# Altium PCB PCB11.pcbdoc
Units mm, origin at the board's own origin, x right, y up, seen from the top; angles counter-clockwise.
Board outline 72.14 x 44.96 mm, 2 copper layers (Top Layer, Bottom Layer); 25 components, 15 nets, 61 pads, 84 vias.
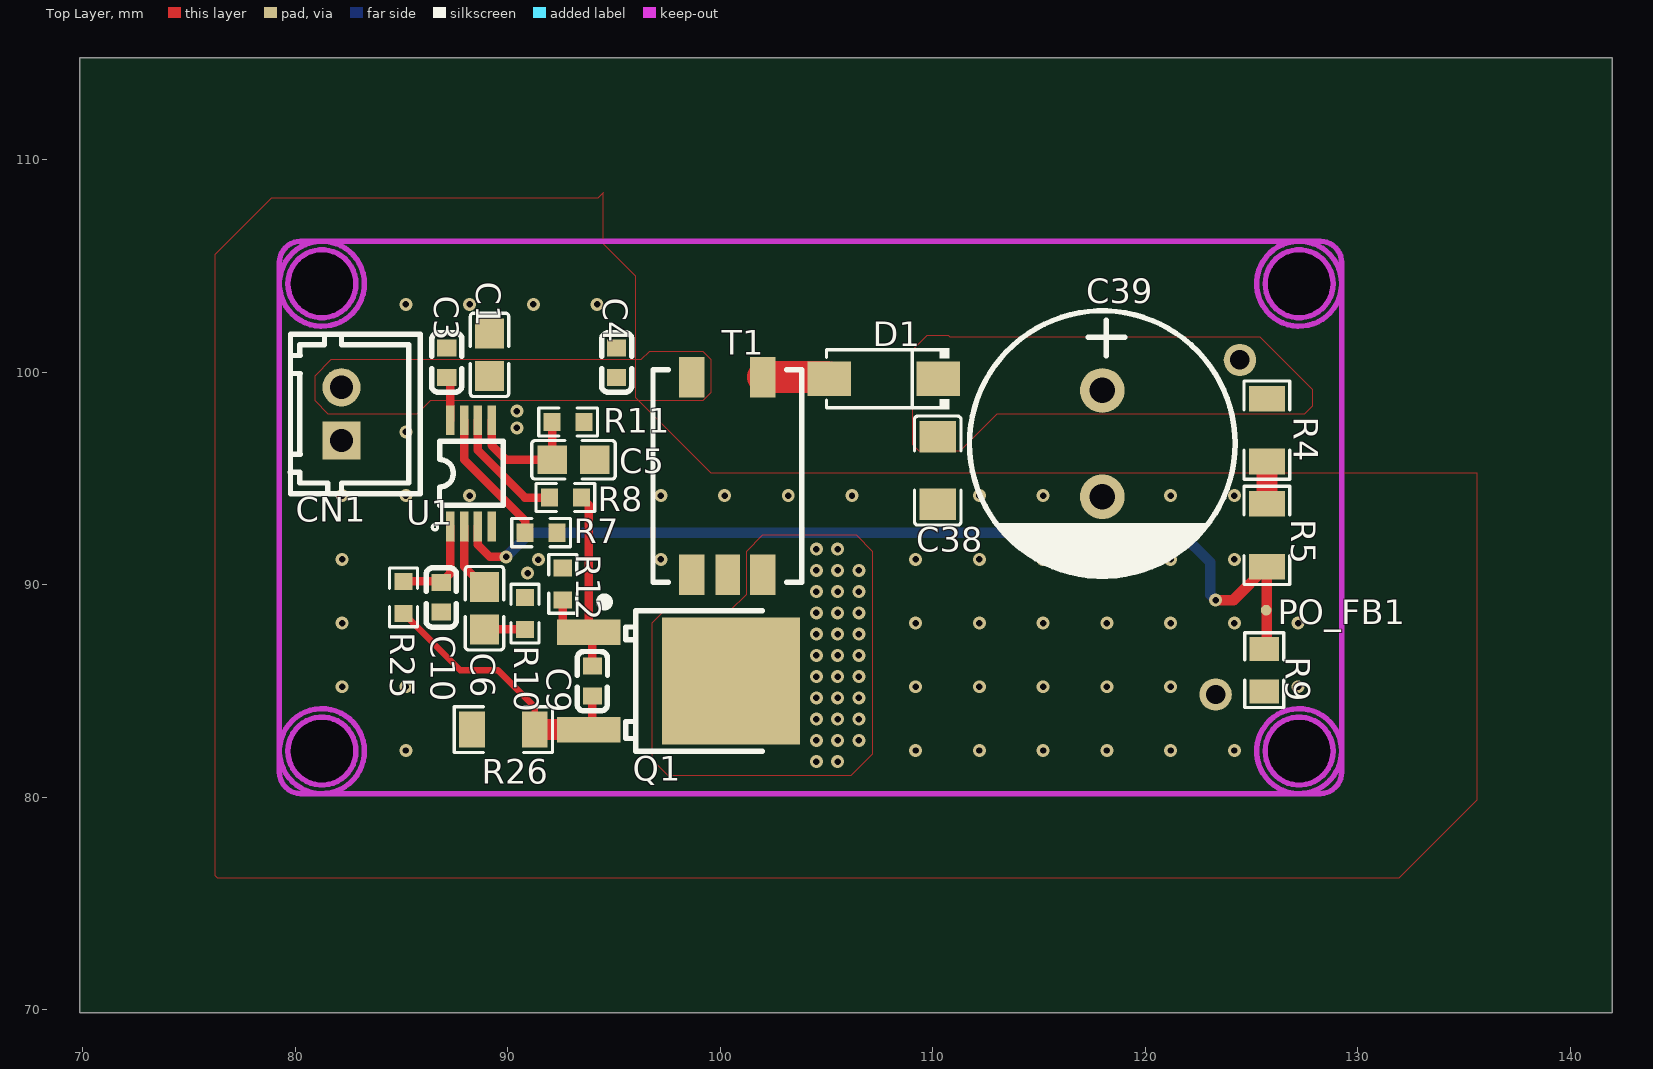
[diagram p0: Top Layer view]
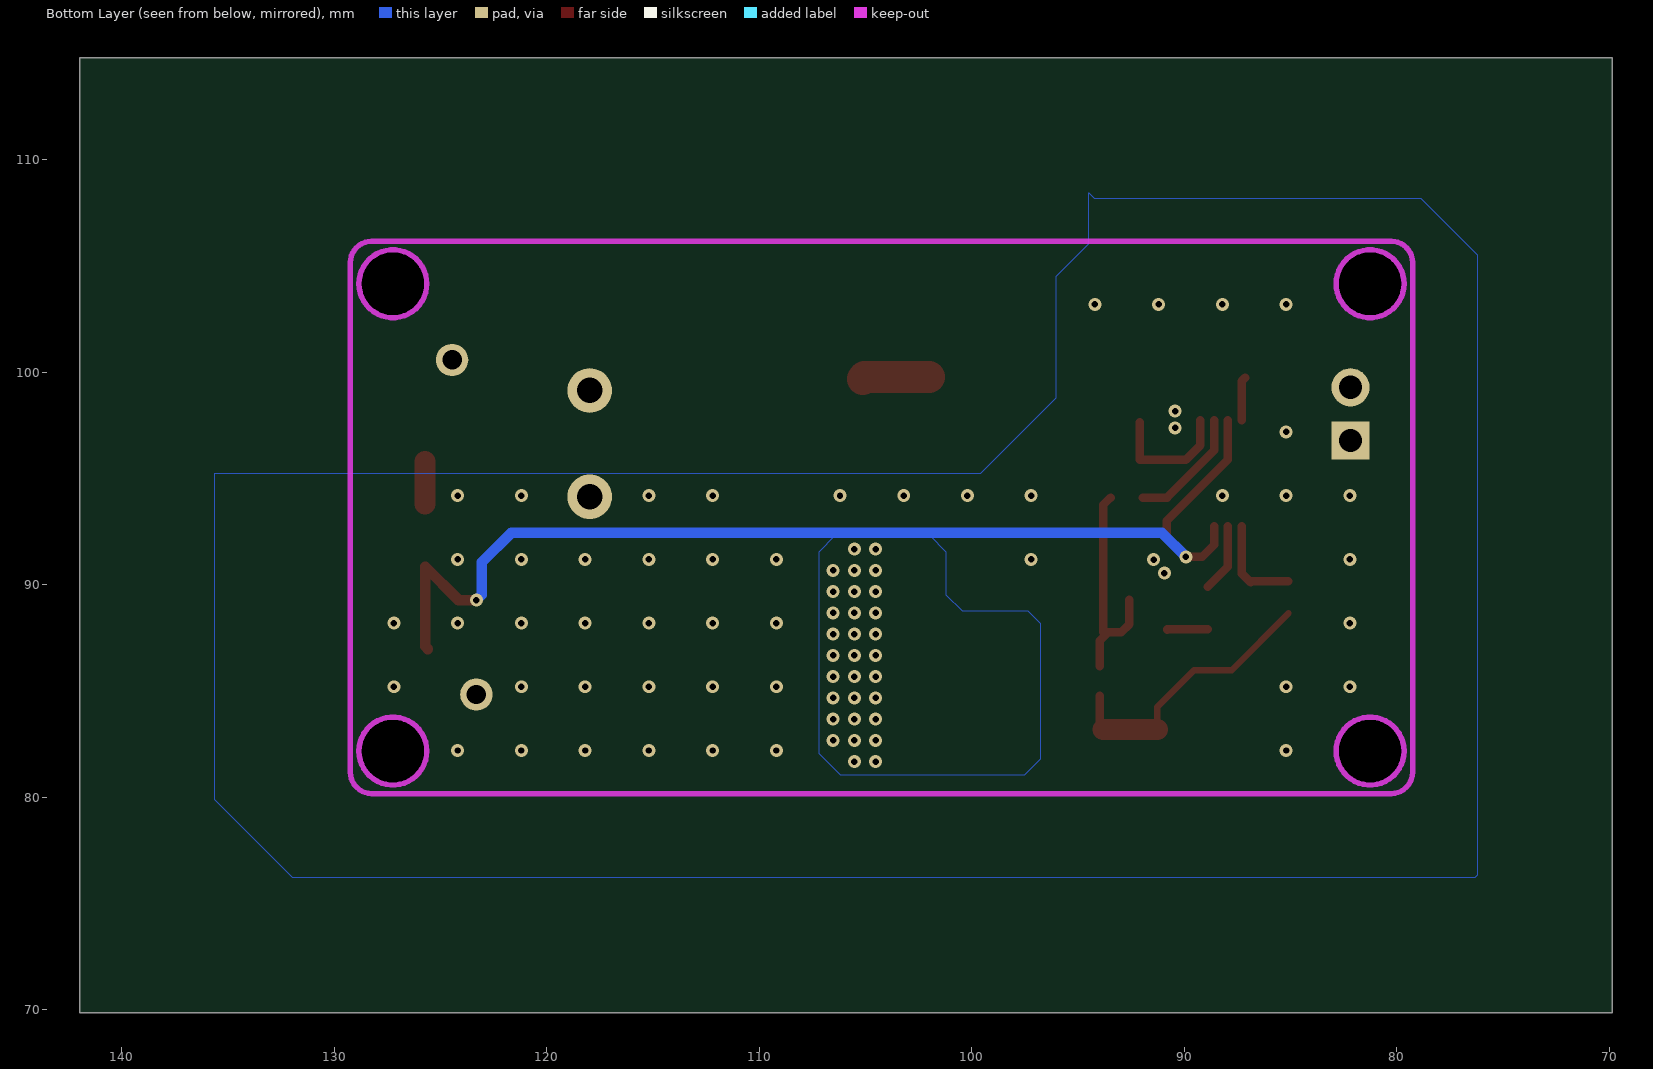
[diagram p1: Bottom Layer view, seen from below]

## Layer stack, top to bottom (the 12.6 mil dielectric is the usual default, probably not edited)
Top Layer: signal copper (thickness not stored)
Dielectric: dielectric 0.32, FR-4, Dk 4.8
Bottom Layer: signal copper (thickness not stored)

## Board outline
141.986,69.85 69.85,69.85 69.85,114.808 141.986,114.808
cut-out: 82.848,104.172 ccw(c81.248,104.163) 79.648,104.172 ccw(c81.248,104.181)
cut-out: 82.848,82.172 ccw(c81.248,82.163) 79.648,82.172 ccw(c81.248,82.181)
cut-out: 128.848,104.172 ccw(c127.248,104.172) 125.648,104.172 ccw(c127.248,104.172)
cut-out: 128.848,82.172 ccw(c127.248,82.172) 125.648,82.172 ccw(c127.248,82.172)

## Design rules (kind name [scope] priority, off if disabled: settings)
Clearance copperThickness1oz [All] p1: gap=0.178 ignorepadtopadclearanceinfootprint=FALSE except(0.102: Track-Track; 0.152: Track-SMDPad SMDPad-SMDPad Track-THPad SMDPad-THPad THPad-THPad Track-Via SMDPad-Via THPad-Via Via-Via Track-Fill SMDPad-Fill THPad-Fill Via-Fill Fill-Fill SMDPad-Region THPad-Region Via-Region Fill-Region Region-Region Track-Poly SMDPad-Poly THPad-Poly Via-Poly Fill-Poly Poly-Poly Track-Text SMDPad-Text THPad-Text Via-Text Fill-Text Region-Text Poly-Text Text-Text Track-Hole SMDPad-Hole THPad-Hole Via-Hole Fill-Hole Region-Hole Poly-Hole Text-Hole; 0.3: Track-Region Region-Poly Track-Sheet SMDPad-Sheet THPad-Sheet Via-Sheet Fill-Sheet Region-Sheet Poly-Sheet Text-Sheet Sheet-Hole)
Clearance copperThickness2oz [All] p1: gap=0.178 ignorepadtopadclearanceinfootprint=FALSE except(0.152: Track-SMDPad SMDPad-SMDPad Track-THPad SMDPad-THPad THPad-THPad Track-Via SMDPad-Via THPad-Via Via-Via Track-Fill SMDPad-Fill THPad-Fill Via-Fill Fill-Fill SMDPad-Region THPad-Region Via-Region Fill-Region Region-Region Track-Poly SMDPad-Poly THPad-Poly Via-Poly Fill-Poly Poly-Poly Track-Text SMDPad-Text THPad-Text Via-Text Fill-Text Region-Text Poly-Text Text-Text Track-Hole SMDPad-Hole THPad-Hole Via-Hole Fill-Hole Region-Hole Poly-Hole Text-Hole; 0.203: Track-Track; 0.3: Track-Region Region-Poly Track-Sheet SMDPad-Sheet THPad-Sheet Via-Sheet Fill-Sheet Region-Sheet Poly-Sheet Text-Sheet Sheet-Hole)
DiffPairsRouting differentialPair [All] p1: maxuncoupledlength=10 maxlimit=5.9843 mostfreqgap=5.9843 toplayer_minwidth=5 toplayer_prefwidth=10 toplayer_maxwidth=100 bottomlayer_minwidth=5 bottomlayer_prefwidth=10 bottomlayer_maxwidth=100
PasteMaskExpansion pasteMaskExpansion [All] p1:
PlaneConnect innerPlane [All] p1: planeconnectstyle=Relief reliefexpansion=0.508 reliefentries=4 reliefconductorwidth=0.254 reliefairgap=0.254
PolygonConnect copperRegion [All] p1: connectstyle=Direct reliefentries=4 reliefconductorwidth=10 polygonreliefangle="90 Angle" airgapwidth=10
RoutingVias viaSize [All] p1: viastyle="Through Hole" holewidth=12.0078 minholewidth=11.811 maxholewidth=248.0314 width=24.0158 minwidth=19.685 maxwidth=393.7008
SolderMaskExpansion solderMaskExpansion [All] p1: useseparateexpansions=TRUE expansion=2.0079 expansionbottom=2.0079
Width copperThickness1oz [All] p1: maxlimit=100 minlimit=5 preferedwidth=10
Width copperThickness2oz [All] p1: maxlimit=100 minlimit=8 preferedwidth=10

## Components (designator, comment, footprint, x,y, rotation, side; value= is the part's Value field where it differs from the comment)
C1 "0805X106K250NT" C0805 89.138,100.822 r270 top
C3 "0603B104K500NT" C0603 87.122,100.457 r270 top
C4 "0603B104K500NT" C0603 95.123,100.457 r270 top
C5 "0805X106K250NT" C0805 93.091,95.885 r180 top
C6 "0805X106K250NT" C0805 88.9,88.9 r90 top
C9 "CC0603KRX7R9BB102" C0603 93.98,85.471 r90 top
C10 "0603B104K500NT" C0603 86.868,89.408 r90 top
C38 "1206B104K251NT_C2909525" C1206 110.236,95.377 r90 top
C39 "EGS2EM470W16OT" CAP-TH_BD12.5-P5.00-D0.6-FD 117.983,96.647 r270 top
CN1 "ZX-XH2.54-2PZZ" CONN-TH_2P-P2.50_HX25003-2A 82.169,98.044 r90 top
D1 "ES1J_C412438" SMA_L4.4-W2.8-LS5.4-RD 107.696,99.695 r180 top
PO_FB1 "Test-Point" Test-Point-0.5mm 125.694,88.807 r0 top
Q1 "NCEP02515K" TO-252-3_L6.6-W6.1-P4.58-LS10.1-BR-2 97.155,85.471 r180 top
R4 "1206W4F1003T5E" R1206 125.73,97.282 r270 top
R5 "1206W4F1003T5E" R1206 125.73,92.329 r270 top
R7 "0603WAF1003T5E" R0603 91.567,92.456 r180 top
R8 "0603WAF100JT5E" R0603 92.71,94.107 r0 top
R9 "0805W8F1501T5E" R0805 125.603,85.979 r90 top
R10 "0603WAF1002T5E" R0603 90.805,88.646 r270 top
R11 "0603WAF200JT5E" R0603 92.837,97.663 r180 top
R12 "0603WAF1002T5E" R0603 92.583,90.043 r270 top
R25 "0603WAF200JT5E" R0603 85.09,89.408 r270 top
R26 "1206W4F100LT5E" R1206 89.789,83.185 r0 top
T1 "TTRN-060S-013-T" TTRN-060S-013 100.33,95.123 r0 top
U1 "SiLM6478-AQ/Boost升压芯片" MSOP-8_L3.0-W3.0-P0.65-LS4.9-TL 88.265,95.25 r90 top

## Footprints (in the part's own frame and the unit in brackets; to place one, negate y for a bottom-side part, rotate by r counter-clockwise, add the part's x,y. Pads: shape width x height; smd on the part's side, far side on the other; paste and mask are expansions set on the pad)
C0603 [mm]
  rect 0.8x0.9 smd: 1(-0.7,0) 2(0.7,0)
  silkscreen extent -1.41,-0.71 1.39,0.72
C0805 [mm]
  rect 1.41x1.35 smd: 1(-1,0) 2(1,0)
  silkscreen extent -1.96,-0.9 1.96,0.9
C1206 [mm]
  rect 1.485x1.728 smd: 1(-1.593,0) 2(1.593,0)
  silkscreen extent -2.56,-1.09 2.56,1.09
CAP-TH_BD12.5-P5.00-D0.6-FD [mm]
  round 2.1 hole 1.2: 1(-2.5,0) 2(2.5,0)
  silkscreen extent -6.25,-6.25 6.25,6.25
CONN-TH_2P-P2.50_HX25003-2A [mm]
  rect 1.8x1.8 hole 1.1: 1(-1.25,0)
  round 1.8 hole 1.1: 2(1.25,0)
  silkscreen extent -3.75,-3.7 3.75,2.41
MSOP-8_L3.0-W3.0-P0.65-LS4.9-TL [mil]
  rect 55x16 smd: 1(-98.5,38.39) 2(-98.5,12.8) 3(-98.5,-12.8) 4(-98.5,-38.39) 5(98.5,-38.39) 6(98.5,-12.8) 7(98.5,12.8) 8(98.5,38.39)
  silkscreen extent -105,-60 60,72
R0603 [mm]
  rect 0.806x0.864 smd: 1(-0.753,0) 2(0.753,0)
  silkscreen extent -1.39,-0.66 1.39,0.66
R0805 [mm]
  rect 1.133x1.377 smd: 1(-1,0) 2(1,0)
  silkscreen extent -1.76,-0.92 1.76,0.92
R1206 [mm]
  rect 1.208x1.701 smd: 1(-1.479,0) 2(1.479,0)
  silkscreen extent -2.31,-1.08 2.31,1.08
SMA_L4.4-W2.8-LS5.4-RD [mm]
  rect 2.046x1.62 smd: 1(-2.565,0) 2(2.565,0)
  silkscreen extent -3.08,-1.44 2.7,1.44
Test-Point-0.5mm [mm]
  round 0.5 smd: 1(0,0)
TO-252-3_L6.6-W6.1-P4.58-LS10.1-BR-2 [mm]
  rect 3x1.2 smd: 1(3.342,-2.285) 3(3.342,2.285)
  rect 6.5x6 smd: 2(-3.343,0)
  silkscreen extent -4.83,-3.92 2.81,3.3
TTRN-060S-013 [mm]
  rect 1.2x1.9 smd: 1(-1.675,4.65) 2(1.675,4.651) 3(-1.675,-4.65) 5(1.675,-4.651)
  rect 1.15x1.9 smd: EMPTY(0.025,-4.65)
  silkscreen extent -3.5,-5 3.5,5

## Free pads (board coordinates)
  round 1.524 hole 0.914: 9(124.46,100.584) 10(123.317,84.836)

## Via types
v1: diameter 0.61, hole 0.304, Top Layer to Bottom Layer, 47 vias
v2: diameter 0.61, hole 0.305, Top Layer to Bottom Layer, 37 vias

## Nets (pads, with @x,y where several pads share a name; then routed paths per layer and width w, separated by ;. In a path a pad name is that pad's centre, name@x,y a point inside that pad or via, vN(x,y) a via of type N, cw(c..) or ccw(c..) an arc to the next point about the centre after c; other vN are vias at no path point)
$1N991: R7.2 U1.7 | length 6.5
  Top Layer w0.4: U1.7 87.94,95.895 90.814,93.022 R7.2
$1N997: C5.2 R11.2 U1.5 | length 6.1
  Top Layer w0.4: U1.5 89.24,96.561 89.916,95.885 C5.2 92.084,95.892 R11.2
$1N1005: C6.1 R10.2 | length 1.9
  Top Layer w0.4: C6.1 90.798,87.9 R10.2
$1N1007: C6.2 U1.2 | length 3.2
  Top Layer w0.4: U1.2 87.94,90.86 C6.2
$1N1020: C9.2 Q1.1 R8.2 R12.2 | length 10.8
  Top Layer w0.4: R12.2 92.583,88.138 92.965,87.756 Q1.1@93.579,87.756 ; R8.2 93.813,93.758 Q1.1 Q1.1@93.579,87.756 ; C9.2 93.98,87.355 Q1.1@93.579,87.756
$1N1033: C9.1 Q1.3 R25.2 R26.2 | length 13.3
  Top Layer w0.3: R25.2 87.766,85.979 89.535,85.979 91.268,84.246 R26.2
  Top Layer w0.4: Q1.3 93.98,83.354 C9.1
  Top Layer w1: R26.2 Q1.3
$1N1040: D1.2 T1.2 | length 3.2
  Top Layer w1.5: T1.2 105.052,99.774 D1.2
$1N1047: R4.2 R5.1 | length 2
  Top Layer w1: R5.1 R4.2
$1N1060: Q1.2 T1.5
  other v2: 104.521,81.678 105.521,81.678 104.521,82.678 105.521,82.678 106.521,82.678 104.521,83.678 105.521,83.678 106.521,83.678 104.521,84.678 105.521,84.678 106.521,84.678 104.521,85.678 105.521,85.678 106.521,85.678 104.521,86.678 105.521,86.678 106.521,86.678 104.521,87.678 105.521,87.678 106.521,87.678 104.521,88.678 105.521,88.678 106.521,88.678 104.521,89.678 105.521,89.678 106.521,89.678 104.521,90.678 105.521,90.678 106.521,90.678 104.521,91.678 105.521,91.678
DR: R8.1 U1.6 | length 5.7
  Top Layer w0.4: U1.6 88.59,96.322 90.805,94.107 R8.1
FB: 
GND: C1.1 C3.1 C4.1 C5.1 C10.1 C38.1 C39.2 CN1.1 pad.10 R7.1 R9.1 R10.1 R11.1 R12.1 R26.1 T1.3 U1.4
  other v1: 85.2,82.2 109.2,82.2 112.2,82.2 115.2,82.2 118.2,82.2 121.2,82.2 124.2,82.2 82.2,85.2 85.2,85.2 109.2,85.2 112.2,85.2 115.2,85.2 118.2,85.2 121.2,85.2 127.2,85.2 82.2,88.2 109.2,88.2 112.2,88.2 115.2,88.2 118.2,88.2 121.2,88.2 124.2,88.2 127.2,88.2 82.2,91.2 97.2,91.2 109.2,91.2 112.2,91.2 115.2,91.2 118.2,91.2 121.2,91.2 124.2,91.2 82.2,94.2 85.2,94.2 88.2,94.2 97.2,94.2 100.2,94.2 103.2,94.2 106.2,94.2 112.2,94.2 115.2,94.2 121.2,94.2 124.2,94.2 85.2,97.2 85.2,103.2 88.2,103.2 91.2,103.2 94.2,103.2
  other v2: 90.932,90.551 91.44,91.186 90.424,97.385 90.424,98.171
HV: C38.2 C39.1 D1.1 pad.9 R4.1
ISEN: C10.2 R25.1 U1.1 | length 4.6
  Top Layer w0.4: R25.1 86.815,90.161 C10.2 87.29,90.53 U1.1
VIN: C1.2 C3.2 C4.2 CN1.2 T1.1 U1.8 | length 2.1
  Top Layer w0.4: C3.2 87.29,99.589 U1.8
pads on no net: PO_FB1.1 R5.2 R9.2 T1.EMPTY U1.3
copper on no net: | length 45.5
  Top Layer w0.4: 88.59,92.748 88.59,91.877 89.154,91.313 v2(89.916,91.313)
  Top Layer w0.5: v2(123.317,89.281) 124.161,89.281 125.73,90.85 125.73,87.106 125.603,86.979
  Bottom Layer w0.5: v2(89.916,91.313) 91.059,92.456 121.666,92.456 123.063,91.059 123.063,89.535 v2(123.317,89.281)

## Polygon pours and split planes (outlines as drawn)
VIN on Top Layer (solid, remove dead copper): 81.661,100.584 80.899,99.822 80.899,98.679 81.534,98.044 85.725,98.044 86.36,98.679 99.187,98.679 99.568,99.06 99.568,100.584 99.187,100.965 96.647,100.965 96.266,100.584
$1N1060 on Bottom Layer (solid, remove dead copper, pour order 10): 101.981,92.329 101.219,91.567 101.219,89.535 100.457,88.773 97.361,88.773 96.774,88.186 96.774,81.788 97.536,81.026 106.172,81.026 107.188,82.042 107.188,91.567 106.426,92.329
$1N1060 on Top Layer (solid, remove dead copper, pour order 4): 101.981,92.329 101.219,91.567 101.219,89.535 100.457,88.773 97.361,88.773 96.774,88.186 96.774,81.788 97.536,81.026 106.172,81.026 107.188,82.042 107.188,91.567 106.426,92.329
GND on Top Layer (solid, remove dead copper, pour order 6): 78.867,108.204 76.2,105.537 76.2,76.327 76.327,76.2 131.953,76.2 135.636,79.883 135.636,95.25 99.568,95.25 96.012,98.806 96.012,104.521 94.488,106.045 94.488,108.458 94.234,108.204
HV on Top Layer (solid, remove dead copper, pour order 8): 109.728,101.727 109.035,101.034 109.035,96.619 109.35,96.303 111.289,96.303 113.03,98.044 127.508,98.044 127.889,98.425 127.889,99.187 125.425,101.651 110.82,101.651 110.744,101.727
GND on Bottom Layer (solid, remove dead copper, pour order 18): 78.867,108.204 76.2,105.537 76.2,76.327 76.327,76.2 131.953,76.2 135.636,79.883 135.636,95.25 99.568,95.25 96.012,98.806 96.012,104.521 94.488,106.045 94.488,108.458 94.234,108.204

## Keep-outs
Top Layer:
  circle w0.254: c81.248,104.172 r2
  circle w0.254: c81.248,82.172 r2
  circle w0.254: c127.248,104.172 r2
  circle w0.254: c127.248,82.172 r2
Board Outline Layer:
  lines w0.254: 79.248,81.172 ccw(c80.248,81.172) 80.248,80.172 128.248,80.172 ccw(c128.248,81.172) 129.248,81.172 129.248,105.172 ccw(c128.248,105.172) 128.248,106.172 80.248,106.172 ccw(c80.248,105.172) 79.248,105.172 79.248,81.172
Multi-Layer:
  circle w0.254: c81.248,104.172 r1.6
  circle w0.254: c81.248,82.172 r1.6
  circle w0.254: c127.248,104.172 r1.6
  circle w0.254: c127.248,82.172 r1.6

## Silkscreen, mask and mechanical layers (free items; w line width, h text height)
Mechanical Layer:
  circle w0.025: c81.248,104.172 r1.6
  circle w0.025: c81.248,82.172 r1.6
  circle w0.025: c127.248,104.172 r1.6
  circle w0.025: c127.248,82.172 r1.6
